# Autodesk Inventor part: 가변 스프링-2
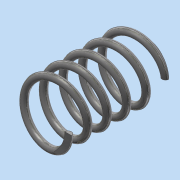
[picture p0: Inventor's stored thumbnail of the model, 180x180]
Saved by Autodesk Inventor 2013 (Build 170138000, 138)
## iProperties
Created: 2018-10
Part Number: 가변 스프링-2
Material: 스테인리스강
Document SubType Name: Modeling
Designer: Administrator
Density: 8.08 g/cm^3
Mass: 6.28229 g
Surface Area: 15.7857 cm^2
Volume: 0.777511 cm^3
Author: Administrator
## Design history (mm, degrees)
sketch "스케치1"
  geometry: L1 (0, 0)-(0, 29.059); L2 (0.539, 0)-(8, 0); L3 (0, 29.059)-(8, 29.059); C1 r 1 at (8, 0)
  constraints: 6 end point, 1 centre point, 1 horizontal alignment, 1 parallel, 1 perpendicular, 1 vertical
  dimensions: "d0" = 29.05875 distance of L1.start L1.end (derived); "d1" = 2 diameter of C1; "d2" = 16 diameter of L2.end L1; "d3" = 8 distance of L1.end L3.end
feature "코일1" sketch "스케치1" pitch "d4" = 10; turns "d6" = 5; dims "d5" = 29.05875 (= d0), "d7" = 0, angle "d8" = 90 deg, angle "d9" = 90 deg, "d10" = 0, "d11" = 0
sketch "스케치2"
  geometry: L1 (29.059, 11)-(0, 11); L2 (0, 11)-(0, -11); L3 (0, -11)-(29.059, -11); L4 (29.059, -11)-(29.059, 11); 2 further points
  constraints: 8 end point, 2 parallel, 1 coincident, 1 horizontal, 1 midpoint, 1 perpendicular
  dimensions: "d12" = 29.05875 distance of L3.end L2.end (derived); "d13" = 22 distance of L2.end L1.end
extrude "돌출1" sketch "스케치2" stored distance "d14" = 0; taper "d15" = 0 deg
node "솔리드1"
